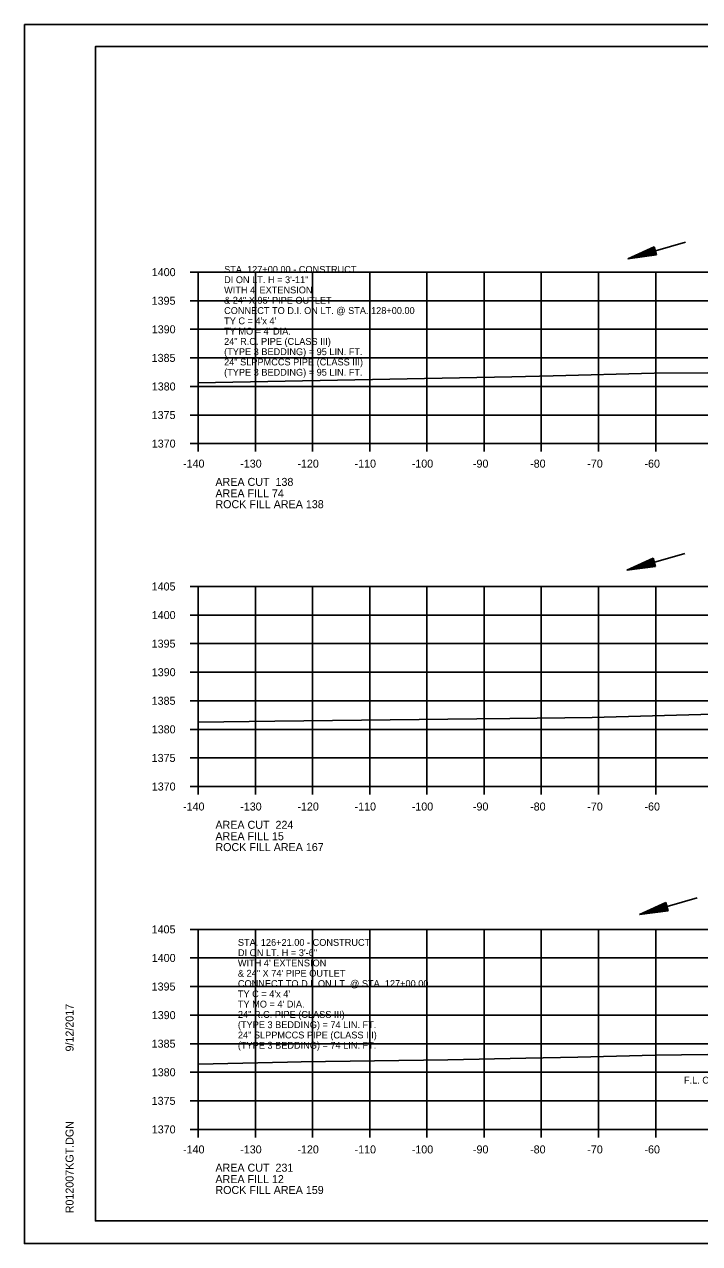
# Model space of a CAD drawing. Extents: x 1374311 to 1383814, y 384102 to 406278.
# Drawn here: x 1381458.2 to 1381576.3, y 386671.3 to 386884.7 of the extents above; entities that cross this region are included whole.
import ezdxf

# ---------------------------------------------------------------- set-up
doc = ezdxf.new("R2010")
doc.units = 0
for name, color, linetype in [('R_Axis', 7, 'Continuous'), ('R_Axis Annot', 7, 'Continuous'), ('R_Border', 7, 'Continuous'), ('R_Draft', 7, 'Continuous'), ('R_Exist Surface', 7, 'Continuous'), ('R_Grid', 7, 'Continuous'), ('R_No Plot', 7, 'Continuous'), ('R_Water', 7, 'Continuous'), ('R_Water Annot', 7, 'Continuous')]:
    doc.layers.add(name, color=color, linetype=linetype)

msp = doc.modelspace()

# ---------------------------------------------------------------- linework, layer by layer
at = {"layer": 'R_Axis'}
for p, q in [((1381487.26, 386841.3), (1381488.66, 386841.3)), ((1381488.66, 386811.3), (1381488.66, 386841.3)), ((1381487.26, 386836.3), (1381488.66, 386836.3)), ((1381487.26, 386831.3), (1381488.66, 386831.3)), ((1381487.26, 386826.3), (1381488.66, 386826.3)), ((1381487.26, 386821.3), (1381488.66, 386821.3)), ((1381487.26, 386816.3), (1381488.66, 386816.3)), ((1381487.26, 386811.3), (1381488.66, 386811.3)), ((1381488.66, 386811.3), (1381768.66, 386811.3)), ((1381488.66, 386809.9), (1381488.66, 386811.3)), ((1381498.66, 386809.9), (1381498.66, 386811.3)), ((1381508.66, 386809.9), (1381508.66, 386811.3)), ((1381518.66, 386809.9), (1381518.66, 386811.3)), ((1381528.66, 386809.9), (1381528.66, 386811.3)), ((1381538.66, 386809.9), (1381538.66, 386811.3)), ((1381548.66, 386809.9), (1381548.66, 386811.3)), ((1381558.66, 386809.9), (1381558.66, 386811.3)), ((1381568.66, 386809.9), (1381568.66, 386811.3)), ((1381487.26, 386786.3), (1381488.66, 386786.3)), ((1381488.66, 386751.3), (1381488.66, 386786.3)), ((1381487.26, 386781.3), (1381488.66, 386781.3)), ((1381487.26, 386776.3), (1381488.66, 386776.3)), ((1381487.26, 386771.3), (1381488.66, 386771.3)), ((1381487.26, 386766.3), (1381488.66, 386766.3)), ((1381487.26, 386761.3), (1381488.66, 386761.3)), ((1381487.26, 386756.3), (1381488.66, 386756.3)), ((1381487.26, 386751.3), (1381488.66, 386751.3)), ((1381488.66, 386751.3), (1381768.66, 386751.3)), ((1381488.66, 386749.9), (1381488.66, 386751.3)), ((1381498.66, 386749.9), (1381498.66, 386751.3)), ((1381508.66, 386749.9), (1381508.66, 386751.3)), ((1381518.66, 386749.9), (1381518.66, 386751.3)), ((1381528.66, 386749.9), (1381528.66, 386751.3)), ((1381538.66, 386749.9), (1381538.66, 386751.3)), ((1381548.66, 386749.9), (1381548.66, 386751.3)), ((1381558.66, 386749.9), (1381558.66, 386751.3)), ((1381568.66, 386749.9), (1381568.66, 386751.3)), ((1381487.26, 386726.3), (1381488.66, 386726.3)), ((1381488.66, 386691.3), (1381488.66, 386726.3)), ((1381487.26, 386721.3), (1381488.66, 386721.3)), ((1381487.26, 386716.3), (1381488.66, 386716.3)), ((1381487.26, 386711.3), (1381488.66, 386711.3)), ((1381487.26, 386706.3), (1381488.66, 386706.3)), ((1381487.26, 386701.3), (1381488.66, 386701.3)), ((1381487.26, 386696.3), (1381488.66, 386696.3)), ((1381487.26, 386691.3), (1381488.66, 386691.3)), ((1381488.66, 386691.3), (1381768.66, 386691.3)), ((1381488.66, 386689.9), (1381488.66, 386691.3)), ((1381498.66, 386689.9), (1381498.66, 386691.3)), ((1381508.66, 386689.9), (1381508.66, 386691.3)), ((1381518.66, 386689.9), (1381518.66, 386691.3)), ((1381528.66, 386689.9), (1381528.66, 386691.3)), ((1381538.66, 386689.9), (1381538.66, 386691.3)), ((1381548.66, 386689.9), (1381548.66, 386691.3)), ((1381558.66, 386689.9), (1381558.66, 386691.3)), ((1381568.66, 386689.9), (1381568.66, 386691.3))]:
    msp.add_line(p, q, dxfattribs=at)
at = {"layer": 'R_Border'}
for p, q in [((1381470.66, 386880.76), (1381786.84, 386880.76)), ((1381470.66, 386675.3), (1381470.66, 386880.76)), ((1381470.66, 386675.3), (1381470.66, 386675.3)), ((1381786.84, 386675.3), (1381470.66, 386675.3))]:
    msp.add_line(p, q, dxfattribs=at)
at = {"layer": 'R_Draft'}
for p, q in [((1381568.39, 386845.76), (1381563.79, 386843.65)), ((1381568.42, 386845.64), (1381564.59, 386843.88)), ((1381568.46, 386845.51), (1381565.42, 386844.12)), ((1381568.49, 386845.39), (1381566.22, 386844.35)), ((1381568.53, 386845.27), (1381567.03, 386844.59)), ((1381568.56, 386845.15), (1381567.84, 386844.82)), ((1381568.39, 386845.76), (1381568.8, 386844.31)), ((1381568.8, 386844.31), (1381563.79, 386843.65)), ((1381568.77, 386844.43), (1381564.59, 386843.88)), ((1381568.73, 386844.56), (1381565.42, 386844.12)), ((1381568.7, 386844.68), (1381566.22, 386844.35)), ((1381568.66, 386844.8), (1381567.03, 386844.59)), ((1381568.63, 386844.92), (1381567.84, 386844.82)), ((1381568.23, 386791.26), (1381563.64, 386789.16)), ((1381568.65, 386789.82), (1381563.64, 386789.16)), ((1381568.27, 386791.14), (1381564.44, 386789.39)), ((1381568.61, 386789.94), (1381564.44, 386789.39)), ((1381568.3, 386791.01), (1381565.26, 386789.62)), ((1381568.58, 386790.06), (1381565.26, 386789.62)), ((1381568.34, 386790.89), (1381566.06, 386789.85)), ((1381568.54, 386790.18), (1381566.06, 386789.85)), ((1381568.37, 386790.77), (1381566.88, 386790.09)), ((1381568.51, 386790.3), (1381566.88, 386790.09)), ((1381568.41, 386790.65), (1381567.68, 386790.32)), ((1381568.47, 386790.42), (1381567.68, 386790.32)), ((1381568.23, 386791.26), (1381568.65, 386789.82)), ((1381570.41, 386731.02), (1381565.81, 386728.91)), ((1381570.44, 386730.89), (1381566.61, 386729.14)), ((1381570.48, 386730.77), (1381567.44, 386729.38)), ((1381570.51, 386730.65), (1381568.24, 386729.61)), ((1381570.72, 386729.94), (1381568.24, 386729.61)), ((1381570.55, 386730.53), (1381569.05, 386729.85)), ((1381570.68, 386730.06), (1381569.05, 386729.85)), ((1381570.58, 386730.41), (1381569.85, 386730.08)), ((1381570.65, 386730.18), (1381569.85, 386730.08)), ((1381570.41, 386731.02), (1381570.82, 386729.57)), ((1381570.82, 386729.57), (1381565.81, 386728.91)), ((1381570.79, 386729.69), (1381566.61, 386729.14)), ((1381570.75, 386729.82), (1381567.44, 386729.38))]:
    msp.add_line(p, q, dxfattribs=at)
at = {"layer": 'R_Exist Surface'}
for points in [[(1381488.66, 386821.94), (1381503.83, 386822.24), (1381543.53, 386823), (1381550.75, 386823.17), (1381568.41, 386823.64), (1381587.17, 386823.74)], [(1381488.66, 386762.57), (1381502.06, 386762.71), (1381537.39, 386763.13), (1381543.17, 386763.2), (1381557.58, 386763.4), (1381578.64, 386763.95)], [(1381488.66, 386702.72), (1381504.29, 386703.08), (1381506.67, 386703.12), (1381532.32, 386703.48), (1381545.96, 386703.77), (1381555.06, 386703.97), (1381568.59, 386704.27), (1381577.78, 386704.4)]]:
    msp.add_lwpolyline(points, dxfattribs=at)
at = {"layer": 'R_Grid'}
for p, q in [((1381488.66, 386841.3), (1381768.66, 386841.3)), ((1381488.66, 386811.3), (1381488.66, 386841.3)), ((1381498.66, 386811.3), (1381498.66, 386841.3)), ((1381508.66, 386811.3), (1381508.66, 386841.3)), ((1381518.66, 386811.3), (1381518.66, 386841.3)), ((1381528.66, 386811.3), (1381528.66, 386841.3)), ((1381538.66, 386811.3), (1381538.66, 386841.3)), ((1381548.66, 386811.3), (1381548.66, 386841.3)), ((1381558.66, 386811.3), (1381558.66, 386841.3)), ((1381568.66, 386811.3), (1381568.66, 386841.3)), ((1381488.66, 386836.3), (1381768.66, 386836.3)), ((1381488.66, 386831.3), (1381768.66, 386831.3)), ((1381488.66, 386826.3), (1381768.66, 386826.3)), ((1381488.66, 386821.3), (1381768.66, 386821.3)), ((1381488.66, 386816.3), (1381768.66, 386816.3)), ((1381488.66, 386811.3), (1381768.66, 386811.3)), ((1381488.66, 386786.3), (1381768.66, 386786.3)), ((1381488.66, 386751.3), (1381488.66, 386786.3)), ((1381498.66, 386751.3), (1381498.66, 386786.3)), ((1381508.66, 386751.3), (1381508.66, 386786.3)), ((1381518.66, 386751.3), (1381518.66, 386786.3)), ((1381528.66, 386751.3), (1381528.66, 386786.3)), ((1381538.66, 386751.3), (1381538.66, 386786.3)), ((1381548.66, 386751.3), (1381548.66, 386786.3)), ((1381558.66, 386751.3), (1381558.66, 386786.3)), ((1381568.66, 386751.3), (1381568.66, 386786.3)), ((1381488.66, 386781.3), (1381768.66, 386781.3)), ((1381488.66, 386776.3), (1381768.66, 386776.3)), ((1381488.66, 386771.3), (1381768.66, 386771.3)), ((1381488.66, 386766.3), (1381768.66, 386766.3)), ((1381488.66, 386761.3), (1381768.66, 386761.3)), ((1381488.66, 386756.3), (1381768.66, 386756.3)), ((1381488.66, 386751.3), (1381768.66, 386751.3)), ((1381488.66, 386726.3), (1381768.66, 386726.3)), ((1381488.66, 386691.3), (1381488.66, 386726.3)), ((1381498.66, 386691.3), (1381498.66, 386726.3)), ((1381508.66, 386691.3), (1381508.66, 386726.3)), ((1381518.66, 386691.3), (1381518.66, 386726.3)), ((1381528.66, 386691.3), (1381528.66, 386726.3)), ((1381538.66, 386691.3), (1381538.66, 386726.3)), ((1381548.66, 386691.3), (1381548.66, 386726.3)), ((1381558.66, 386691.3), (1381558.66, 386726.3)), ((1381568.66, 386691.3), (1381568.66, 386726.3)), ((1381488.66, 386721.3), (1381768.66, 386721.3)), ((1381488.66, 386716.3), (1381768.66, 386716.3)), ((1381488.66, 386711.3), (1381768.66, 386711.3)), ((1381488.66, 386706.3), (1381768.66, 386706.3)), ((1381488.66, 386701.3), (1381768.66, 386701.3)), ((1381488.66, 386696.3), (1381768.66, 386696.3)), ((1381488.66, 386691.3), (1381768.66, 386691.3))]:
    msp.add_line(p, q, dxfattribs=at)
at = {"layer": 'R_No Plot'}
for p, q in [((1381458.26, 386884.66), (1381791.59, 386884.66)), ((1381458.26, 386671.32), (1381791.59, 386671.32))]:
    msp.add_line(p, q, dxfattribs=at)
for points in [[(1381458.25, 386884.66), (1381791.59, 386884.66), (1381791.59, 386671.32), (1381458.25, 386671.32)], [(1381704.58, 386880.76), (1381704.58, 386870.88), (1381740.31, 386870.88), (1381740.31, 386867.96), (1381763.51, 386867.96), (1381763.51, 386844.75), (1381786.84, 386844.75), (1381786.84, 386675.3), (1381470.66, 386675.3), (1381470.66, 386880.76)]]:
    msp.add_lwpolyline(points, close=True, dxfattribs=at)
at = {"layer": 'R_Water'}
for p, q in [((1381573.89, 386846.55), (1381563.79, 386843.65)), ((1381573.73, 386792.06), (1381563.64, 386789.16)), ((1381575.91, 386731.81), (1381565.81, 386728.91))]:
    msp.add_line(p, q, dxfattribs=at)

# ---------------------------------------------------------------- texts
at = {"layer": 'R_Axis Annot'}
for s, p in [('1400', (1381480.53, 386840.6)), ('1395', (1381480.51, 386835.6)), ('1390', (1381480.53, 386830.6)), ('1385', (1381480.51, 386825.6)), ('1380', (1381480.53, 386820.6)), ('1375', (1381480.51, 386815.6)), ('1370', (1381480.53, 386810.6)), ('-140', (1381486, 386807.1)), ('-130', (1381496, 386807.1)), ('-120', (1381506, 386807.1)), ('-110', (1381516, 386807.1)), ('-100', (1381526, 386807.1)), ('-90', (1381536.7, 386807.1)), ('-80', (1381546.7, 386807.1)), ('-70', (1381556.7, 386807.1)), ('-60', (1381566.7, 386807.1)), ('AREA CUT  138', (1381491.66, 386803.9)), ('AREA FILL 74', (1381491.66, 386801.9)), ('ROCK FILL AREA 138', (1381491.66, 386800)), ('1405', (1381480.51, 386785.6)), ('1400', (1381480.53, 386780.6)), ('1395', (1381480.51, 386775.6)), ('1390', (1381480.53, 386770.6)), ('1385', (1381480.51, 386765.6)), ('1380', (1381480.53, 386760.6)), ('1375', (1381480.51, 386755.6)), ('1370', (1381480.53, 386750.6)), ('-140', (1381486, 386747.1)), ('-130', (1381496, 386747.1)), ('-120', (1381506, 386747.1)), ('-110', (1381516, 386747.1)), ('-100', (1381526, 386747.1)), ('-90', (1381536.7, 386747.1)), ('-80', (1381546.7, 386747.1)), ('-70', (1381556.7, 386747.1)), ('-60', (1381566.7, 386747.1)), ('AREA CUT  224', (1381491.66, 386743.9)), ('AREA FILL 15', (1381491.66, 386741.9)), ('ROCK FILL AREA 167', (1381491.66, 386740)), ('1405', (1381480.51, 386725.6)), ('1400', (1381480.53, 386720.6)), ('1395', (1381480.51, 386715.6)), ('1390', (1381480.53, 386710.6)), ('1385', (1381480.51, 386705.6)), ('1380', (1381480.53, 386700.6)), ('1375', (1381480.51, 386695.6)), ('1370', (1381480.53, 386690.6)), ('-140', (1381486, 386687.1)), ('-130', (1381496, 386687.1)), ('-120', (1381506, 386687.1)), ('-110', (1381516, 386687.1)), ('-100', (1381526, 386687.1)), ('-90', (1381536.7, 386687.1)), ('-80', (1381546.7, 386687.1)), ('-70', (1381556.7, 386687.1)), ('-60', (1381566.7, 386687.1)), ('AREA CUT  231', (1381491.66, 386683.9)), ('AREA FILL 12', (1381491.66, 386681.9)), ('ROCK FILL AREA 159', (1381491.66, 386680))]:
    msp.add_text(s, height=1.4, dxfattribs=at).set_placement(p)
at = {"layer": 'R_Border'}
for s, p in [('9/12/2017', (1381466.85, 386704.94)), ('R012007KGT.DGN', (1381466.85, 386676.63))]:
    msp.add_text(s, height=1.4, rotation=90, dxfattribs=at).set_placement(p)
at = {"layer": 'R_Water'}
msp.add_text('F.L. OUTLET LT. = 1380.53', height=1.2, dxfattribs=at).set_placement((1381573.61, 386699.32))
at = {"layer": 'R_Water Annot'}
for s, p in [('STA. 127+00.00 - CONSTRUCT', (1381493.18, 386841.18)), ("WITH 4' EXTENSION ", (1381493.18, 386837.58)), ('DI ON LT. H = 3\'-11"', (1381493.18, 386839.38)), ('& 24" X 95\' PIPE OUTLET', (1381493.18, 386835.78)), ('CONNECT TO D.I. ON LT. @ STA. 128+00.00', (1381493.18, 386833.98)), ("TY C = 4'x 4'", (1381493.18, 386832.18)), ("TY MO = 4' DIA.", (1381493.18, 386830.38)), ('24" R.C. PIPE (CLASS III)', (1381493.18, 386828.58)), ('(TYPE 3 BEDDING) = 95 LIN. FT.', (1381493.18, 386826.78)), ('24" SLPPMCCS PIPE (CLASS III)', (1381493.18, 386824.98)), ('(TYPE 3 BEDDING) = 95 LIN. FT.', (1381493.18, 386823.18)), ('STA. 126+21.00 - CONSTRUCT', (1381495.59, 386723.42)), ('DI ON LT. H = 3\'-6"', (1381495.59, 386721.62)), ("WITH 4' EXTENSION ", (1381495.59, 386719.82)), ('& 24" X 74\' PIPE OUTLET', (1381495.59, 386718.02)), ('CONNECT TO D.I. ON LT. @ STA. 127+00.00', (1381495.59, 386716.22)), ("TY C = 4'x 4'", (1381495.59, 386714.42)), ("TY MO = 4' DIA.", (1381495.59, 386712.62)), ('24" R.C. PIPE (CLASS III)', (1381495.59, 386710.82)), ('(TYPE 3 BEDDING) = 74 LIN. FT.', (1381495.59, 386709.02)), ('24" SLPPMCCS PIPE (CLASS III)', (1381495.59, 386707.22)), ('(TYPE 3 BEDDING) = 74 LIN. FT.', (1381495.59, 386705.42))]:
    msp.add_text(s, height=1.2, dxfattribs=at).set_placement(p)

doc.saveas('drawing.dxf')
